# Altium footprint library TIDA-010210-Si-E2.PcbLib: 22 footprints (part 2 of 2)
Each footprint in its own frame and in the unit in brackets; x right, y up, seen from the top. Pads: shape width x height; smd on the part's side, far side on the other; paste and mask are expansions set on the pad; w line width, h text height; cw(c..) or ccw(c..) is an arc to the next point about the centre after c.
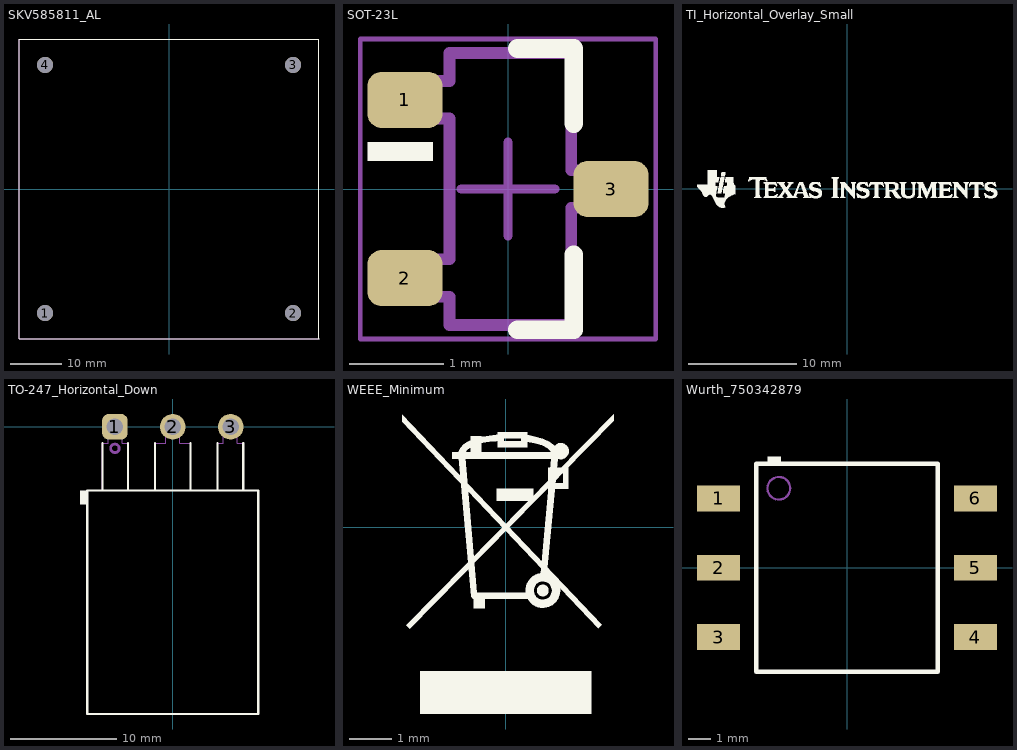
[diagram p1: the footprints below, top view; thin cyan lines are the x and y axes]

## SKV585811_AL [mm] "HeatSink"
height 11
pads (4):
  round 3.1 hole 3.1 unplated mask+0.178: 1(-24,-24) 2(24,-24) 3(24,24) 4(-24,24)
Top Overlay:
  lines w0.152: -29,-29 0,-29 29,-29 29,0 29,29 0,29 -29,29 -29,0 -29,-29
Mechanical 5:
  lines w0.152: -29,-29 -29,0 -29,29 0,29 29,29 29,0 29,-29 0,-29 -29,-29
  text ".Designator" at -28.705,28.14 h0.46
Mechanical 13:
  lines w0.152: -29.044,-28.956 -29,-29
3D body "AL_SKV585811.step": height 21, standoff 3.25, extent -29,-29 29,29

## SOT-23L [mm] "SOT23, 3-Leads, Body 2.9x1.3mm, Pitch 0.95mm, Lead Span 2.5mm, IPC High Density"
height 1.1
pads (3):
  rrect50% 0.8x0.6 smd: 1(-1.1,0.95) 2(-1.1,-0.95) 3(1.1,0)
Top Overlay:
  rectangle: -1.5,0.3 -0.8,0.5
  lines w0.2: 0.1,-1.5 0.7,-1.5 0.7,-0.7 ; 0.1,1.5 0.7,1.5 0.7,0.7
Mechanical 5:
  lines w0.127: -1.16,-1.15 -0.625,-1.15 -0.625,-1.45 0.675,-1.45 0.675,-0.2 1.21,-0.2 1.21,0.2 0.675,0.2 0.675,1.45 -0.625,1.45 -0.625,1.15 -1.16,1.15 -1.16,0.75 -0.625,0.75 -0.625,-0.75 -1.16,-0.75 -1.16,-1.15
  text ".Designator" at 0.333,0.186 h0.46
Mechanical 15:
  lines w0.05: -1.575,-1.6 -1.575,1.6 1.575,1.6 1.575,-1.6 -1.575,-1.6
  lines w0.1: -0.5,0 0.5,0 ; 0,-0.5 0,0.5
3D body "SW3dPS-sot-3p290x130ll237h100.STEP": height 1, standoff 0, extent -1.16,-1.45 1.21,1.45

## TI_Horizontal_Overlay_Small [mm]
Top Overlay:
  drawing of 18 lines, arcs and shapes, not listed

## TO-247_Horizontal_Down [mil] "TH, 3-Leads, Body 16.13x 21.1mm, Pitch 5.461mm"
height 205.12
pads (3):
  rrect50% 95x95 hole 62: 1(-215,0)
  round 95 / inner round 74.8 / far side round 96 hole 62: 2(0,0) 3(215,0)
Top Overlay:
  rectangle: -345.54,-288 -318.03,-236.89
  lines w7.87: -261.61,-236.22 -261.61,-60.24 ; -166.73,-236.22 -166.73,-60.24 ; -66.54,-236.22 -66.54,-60.24 ; 66.54,-236.22 66.54,-60.24 ; 166.73,-236.22 166.73,-60.24 ; 261.61,-236.22 261.61,-60.24 ; -317.52,-1066.93 -317.52,-236.22 317.52,-236.22 317.52,-1066.93 -317.52,-1066.93
Mechanical 5:
  circle w10: c-215,-80 r15.81
  lines w3.94: -261.61,-236.22 -261.61,-60.24 -240.35,-60.24 -240.35,-31.5 ; -166.73,-236.22 -166.73,-60.24 -187.99,-60.24 -187.99,-31.5 ; -66.54,-236.22 -66.54,-60.24 -26.18,-60.24 -26.18,-31.5 ; 66.54,-236.22 66.54,-60.24 26.18,-60.24 26.18,-31.5 ; 166.73,-236.22 166.73,-60.24 187.99,-60.24 187.99,-31.5 ; 261.61,-236.22 261.61,-60.24 240.35,-60.24 240.35,-31.5 ; -240.35,-31.5 -240.35,13.39 -187.99,13.39 -187.99,-31.5 ; -240.35,-31.5 -187.99,-31.5 ; -26.18,-31.5 -26.18,13.39 26.18,13.39 26.18,-31.5 ; -26.18,-31.5 26.18,-31.5 ; 187.99,-31.5 187.99,13.39 240.35,13.39 240.35,-31.5 ; 187.99,-31.5 240.35,-31.5 ; -317.52,-1066.93 317.52,-1066.93 317.52,-236.22 -317.52,-236.22 -317.52,-1066.93
  text ".Designator" at 24.2,-641 h18
3D body "TO-247_Horizontal_Down.stp": height 205.12, standoff -321.65, extent -317.52,-1066.93 317.52,13.39

## WEEE_Minimum [mm] "WEEElie bin"
height 19.05
Top Overlay:
  drawing of 23 lines, arcs and shapes, not listed

## Wurth_750342879 [mm] "SMD, 6-Leads, Body 9.14x8mm, Pitch 3.05mm"
height 7.62
pads (6):
  rect 1.9x1.14 smd: 1(-5.655,3.05) 2(-5.655,0) 3(-5.655,-3.05) 4(5.655,-3.05) 5(5.655,0) 6(5.655,3.05)
Top Overlay:
  rectangle: -3.5,4.57 -2.9,4.9
  lines w0.2: -4,-4.57 4,-4.57 4,4.57 -4,4.57 -4,-4.57
Mechanical 5:
  circle w0.1: c-3,3.5 r0.5
  lines w0.1: -4,-4.57 -4,4.57 4,4.57 4,-4.57 -4,-4.57
  text ".Designator" at -0.711,-0.356 h0.46
3D body: height 6.5, standoff 5, extent -2,-4.57 2,4.57
3D body: height 7.82, standoff 6.5, extent -4,-4.57 4,4.57
3D body: height 5, standoff 0, extent -4,-4.57 4,4.57
3D body: height 7.83, standoff 7.8, extent -3.499,3.001 -2.501,3.999
3D body: height 0.8, standoff 0, extent -6.35,2.75 -3.849,3.35
3D body: height 0.8, standoff 0, extent -6.35,-0.3 -3.849,0.3
3D body: height 0.8, standoff 0, extent -6.35,-3.35 -3.849,-2.75
3D body: height 0.8, standoff 0, extent 3.849,-3.35 6.35,-2.75
3D body: height 0.8, standoff 0, extent 3.849,-0.3 6.35,0.3
3D body: height 0.8, standoff 0, extent 3.849,2.75 6.35,3.35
